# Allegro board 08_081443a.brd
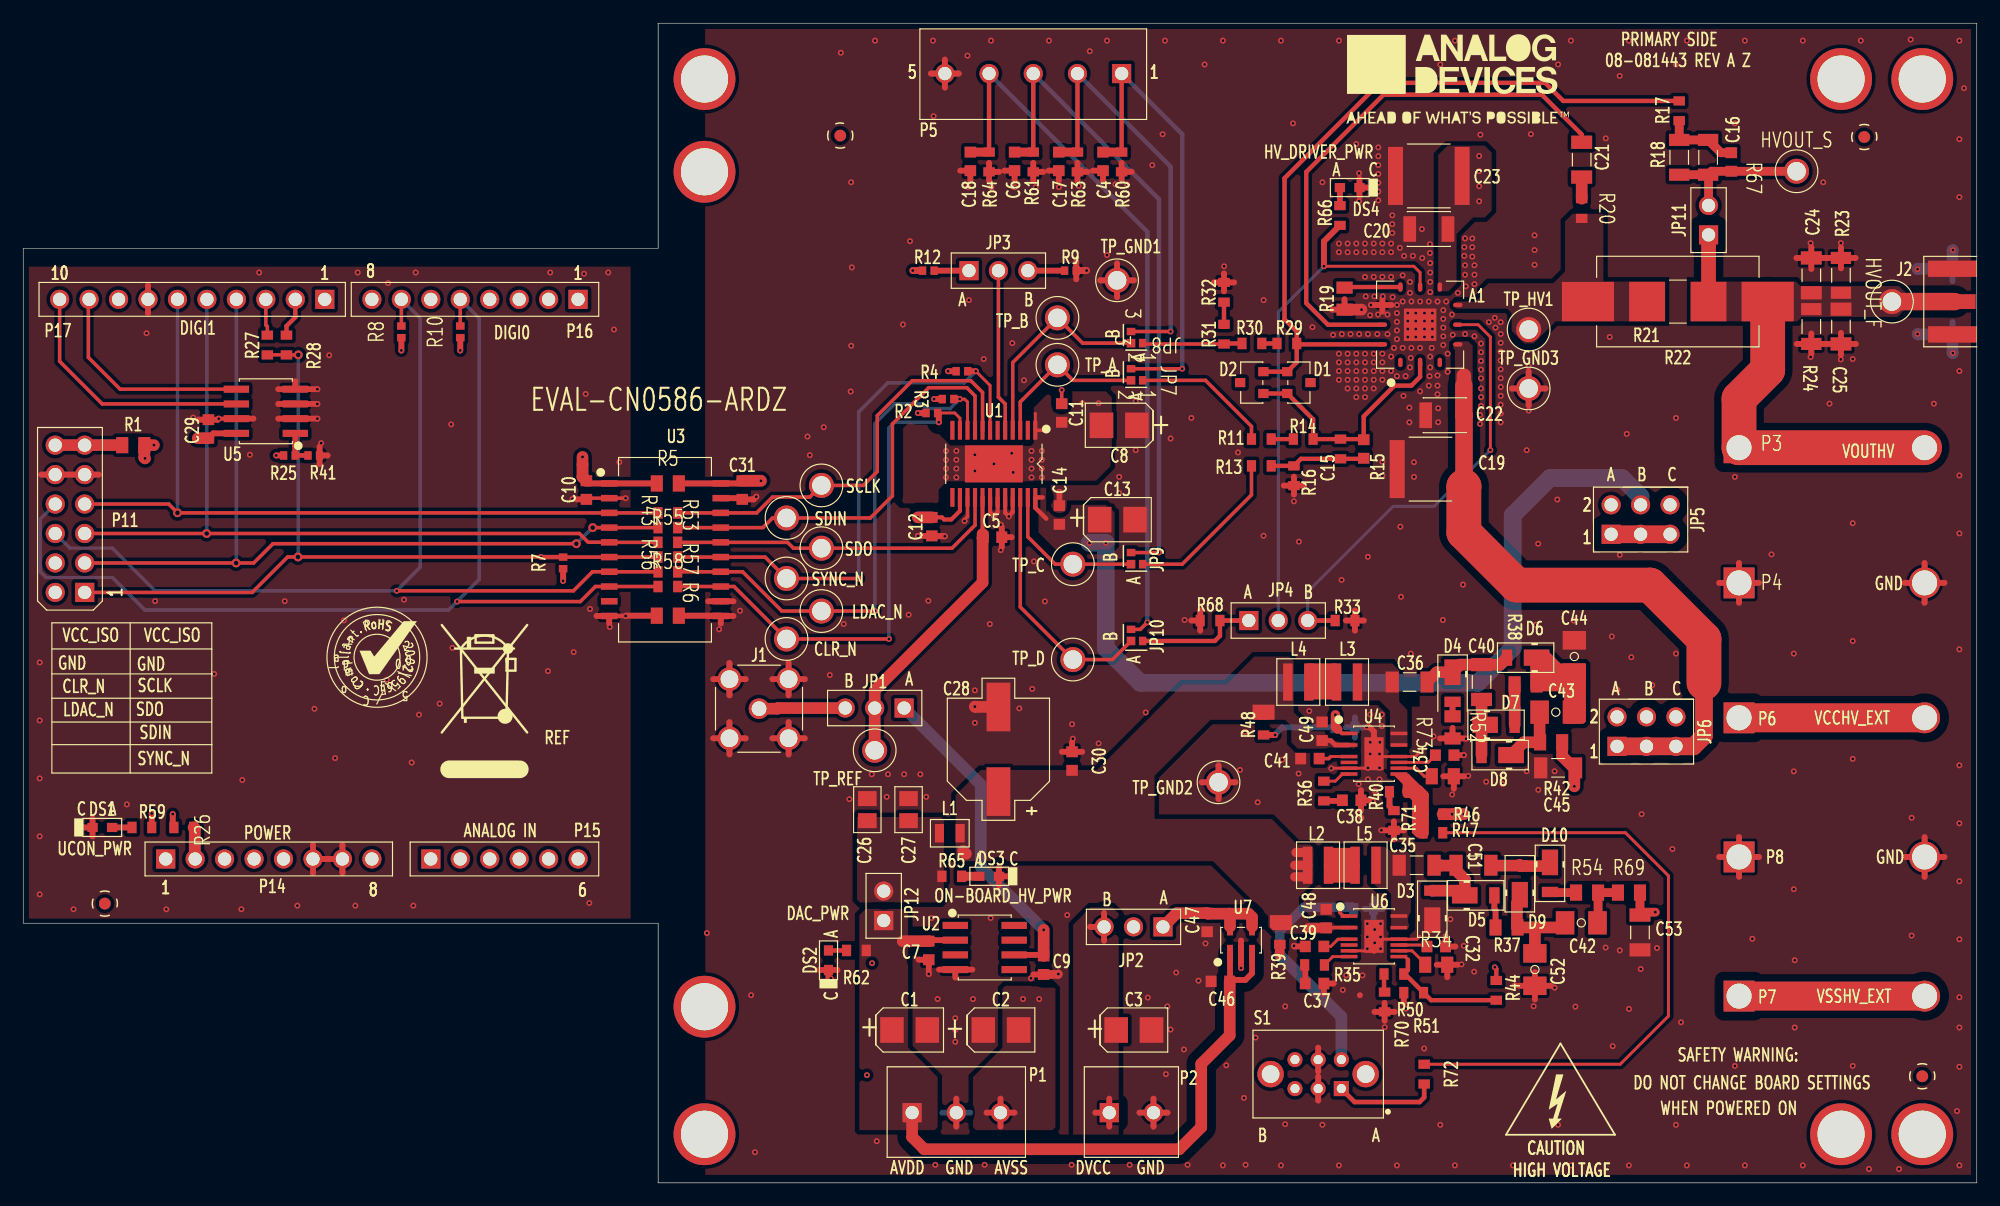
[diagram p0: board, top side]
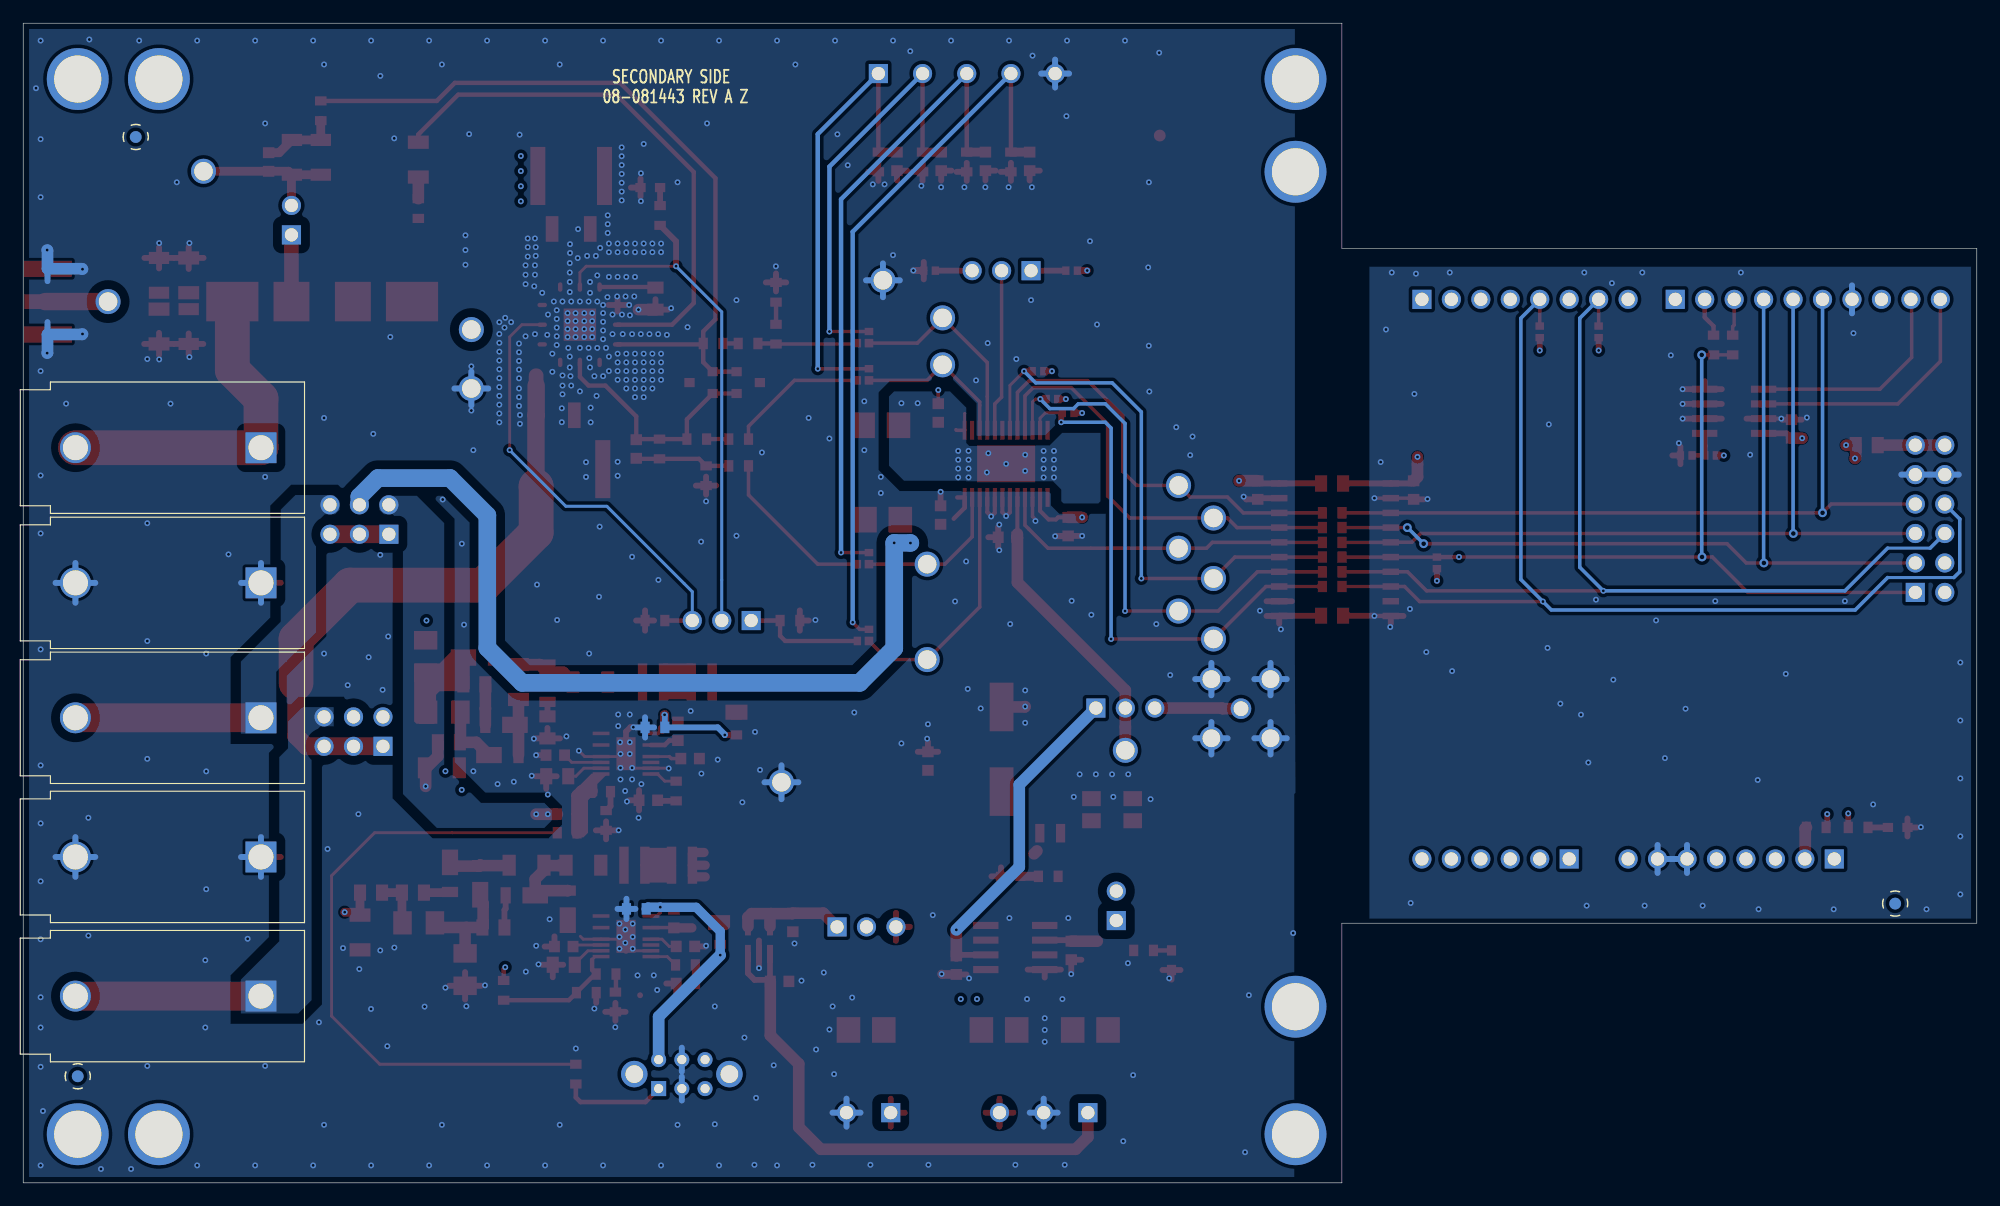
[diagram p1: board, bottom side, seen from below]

Outline 168.45 x 100 mm; copper layers: TOP, L2_GND, L3_PWR, BOTTOM. Coordinates in mm from the lower left corner of the outline.
Outline path: 0,80.59 0,22.39 54.74,22.39 54.74,0 168.45,0 168.45,100 54.74,100 54.74,80.59 0,80.59

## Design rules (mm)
constraint set DEFAULT: min track width 0.203
net group 200V: nets 15V_FLT AVSS UNNAMED_5_ADHV4702_I35_VCC UNNAMED_5_ADHV4702_I35_VEE VCCHV_EXT

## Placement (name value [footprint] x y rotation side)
A1  ADHV4702-1BCPZ  [QFN12_7X7_PAD2_8X2_8]  120.45 74 0 top
C1  10uF  [C3528]  76.43 13.18 0 top
C2  10uF  [C3528]  84.31 13.18 0 top
C3  10uF  [C3528]  95.77 13.18 0 top
C4  200pF  [C0603]  93.11 88.08 270 top
C5  0.1uF  [C0603]  83.58 55.67 180 top
C6  200pF  [C0603]  85.48 88.08 270 top
C7  0.1uF  [C0603]  78.08 20.04 90 top
C8  10uF  [C3528]  94.5 65.33 180 top
C9  0.1uF  [C0603]  87.99 18.77 90 top
C10  0.1uF  [C0603]  48.56 59.74 270 top
C11  0.1uF  [C0603]  89.55 66.39 90 top
C12  0.1uF  [C0603]  78.35 56.59 90 top
C13  10uF  [C3528]  94.35 57.19 0 top
C14  0.1uF  [C0603]  89.34 57.59 270 top
C15  2pF  [C0603]  115.59 63.28 270 top
C16  2pF  [C0603]  147.28 88.03 270 top
C17  200pF  [C0603]  89.29 88.08 270 top
C18  200pF  [C0603]  81.67 88.08 270 top
C19  2.2uF  [C2220-4]  121.35 61.55 0 top
C20  0.1uF  [C1210H87]  121.2 82.26 180 top
C21  100pF  [C1206]  134.38 88.23 90 top
C22  0.1uF  [C1210H87]  122.57 66.19 180 top
C23  2.2uF  [C2220-4]  121.2 86.83 180 top
C24  100pF  [C1206]  154.18 78.26 90 top
C25  100pF  [C1206]  156.74 73.84 270 top
C26  4.7uF  [C0805H53]  72.78 32.18 270 top
C27  4.7uF  [C0805H53]  76.34 32.18 270 top
C28  68uF  [CPLSMSQ327H413]  84.09 37.39 90 top
C29  0.1uF  [C0603]  15.97 65.01 90 top
C30  10uF  [C0603]  90.44 36.37 270 top
C31  0.1uF  [C0603]  62 59.74 270 top
C32  0.22uF  [C0603]  121.84 20.38 0 top
C34  0.22uF  [C0603]  122.57 36.88 0 top
C35  0.1UF  [C1206]  120.14 27.39 0 top
C36  0.1UF  [C1206]  119.55 43.19 0 top
C37  2200pF  [C0603]  111.35 17.19 0 top
C38  2200pF  [C0603]  114.55 32.99 0 top
C39  1uF  [C0603]  111.35 20.39 180 top
C40  0.1UF  [C1206]  125.75 43.19 270 top
C41  1uF  [C0603]  110.94 36.59 180 top
C42  0.22UF  [C1206H71]  134.35 22.42 180 top
C43  0.22UF  [C1206H71]  132.15 40.59 0 top
C44  0.22UF  [C1206H71]  133.75 45.39 90 top
C45  0.1UF  [C1206]  132.35 35.79 180 top
C46  2.2uF  [C0603]  103.23 17.37 180 top
C47  2.2uF  [C0603]  102.09 22.45 270 top
C48  1uF  [C0603]  112.35 22.79 90 top
C49  1uF  [C0603]  112 38.94 90 top
C51  0.1UF  [C1206]  125.05 27.39 0 top
C52  0.22UF  [C1206H71]  130.35 18.39 270 top
C53  0.1UF  [C1206]  139.41 21.59 270 top
CLR_N  WHT  [CNLOOPTP]  65.82 46.9 0 top
D1  BAV199LT1G  [SOT23-M3]  109.99 69.01 270 top
D2  BAV199LT1G  [SOT23-M3]  105.93 69.01 90 top
D3  DFLS1150-7  [POWERDI123]  121.5 23.59 90 top
D4  DFLS1150-7  [POWERDI123]  123.25 43.09 270 top
D5  DFLS1150-7  [POWERDI123]  125.24 24.79 0 top
D6  DFLS1150-7  [POWERDI123]  129.55 45.29 180 top
D7  DFLS1150-7  [POWERDI123]  126.99 39.49 0 top
D8  DFLS1150-7  [POWERDI123]  127.35 36.89 180 top
D9  DFLS1150-7  [POWERDI123]  129.04 25.79 90 top
D10  DFLS1150-7  [POWERDI123]  131.65 26.69 270 top
DS1  SML-D12P8WT86  [LED0603_A]  6.82 30.65 0 top
DS2  SML-D12P8WT86  [LED0603_A]  69.44 19.19 90 top
DS3  SML-D12P8WT86  [LED0603_A]  83.29 26.43 180 top
DS4  SML-D12P8WT86  [LED0603_A]  114.38 85.83 180 top
HVOUT_F  RED  [CNLOOPTP]  161.13 75.99 0 top
HVOUT_S  RED  [CNLOOPTP]  152.9 87.23 0 top
J1  1-1337482-0  [CNBNCSQ276H299]  63.45 40.89 0 top
J2  SMA-J-P-H-ST-EM1  [CNSAMTECSMA-JPX-ST-EM1-MKT]  168.45 75.99 0 top
JP1  M20-9990345  [CNHDR1X3H340]  75.96 40.94 180 top
JP2  M20-9990345  [CNHDR1X3H340]  98.28 22.07 180 top
JP3  M20-9990345  [CNHDR1X3H340]  81.55 78.66 0 top
JP4  M20-9990345  [CNHDR1X3H340]  105.68 48.49 0 top
JP5  TSW-103-07-G-D  [CNTHMHDR2X3L300W200H343_TL]  136.92 55.93 0 top
JP6  TSW-103-07-G-D  [CNTHMHDR2X3L300W200H343_TL]  137.43 37.64 0 top
JP7  0  [3PINJUMPER_0402]  95.52 69.2 270 top
JP8  0  [3PINJUMPER_0402]  95.52 72.41 270 top
JP9  0  [3PINJUMPER_0402]  95.52 53.35 270 top
JP10  0  [3PINJUMPER_0402]  95.52 46.73 270 top
JP11  TSW-102-08-G-S  [CNSAMTEC1X2H330LD36]  145.32 83.02 90 top
JP12  TSW-102-08-G-S  [CNSAMTEC1X2H330LD36]  74.2 23.89 90 top
L1  0.47UH  [L0806H39]  79.9 30.15 0 top
L2  6.8UH  [LSML126W138H118]  111.65 27.39 0 top
L3  6.8UH  [LSML126W138H118]  114.15 43.19 0 top
L4  6.8UH  [LSML126W138H118]  109.95 43.19 0 top
L5  6.8UH  [LSML126W138H118]  115.75 27.39 0 top
LDAC_N  WHT  [CNLOOPTP]  68.83 49.31 0 top
NOREF  -  []  30.51 45.32 0 top
NOREF#2  -  [unnamed#2]  156.75 95.19 0 top
NOREF#3  -  []  54.74 100 0 top
NOREF#4  -  [unnamed#2]  58.75 15.19 0 top
NOREF#5  -  [unnamed#2]  163.75 9.19 0 top
NOREF#6  -  []  0.01 80.59 0 top
NOREF#7  -  []  54.74 0 0 top
NOREF#8  -  []  54.74 0 0 top
NOREF#9  -  []  58.75 4.19 0 top
NOREF#10  -  []  168.45 0 90 top
NOREF#11  -  [unnamed#2]  163.75 4.19 0 top
NOREF#12  -  []  -109.94 -160.87 0 top
NOREF#13  -  []  58.75 4.19 0 top
NOREF#14  -  []  0.01 80.59 0 top
NOREF#15  -  [unnamed#2]  58.75 87.19 0 top
NOREF#16  -  []  -109.94 -158.67 0 top
NOREF#17  -  [unnamed#2]  163.75 95.19 0 top
NOREF#18  -  []  123.71 95.17 0 top
NOREF#19  -  []  -114.94 -160.87 0 top
NOREF#20  -  [unnamed#2]  156.75 4.19 0 top
NOREF#21  -  []  168.45 0 0 top
NOREF#22  -  []  132.3 6.94 0 top
NOREF#23  -  []  49.04 51.79 0 top
NOREF#24  -  [unnamed#2]  58.75 4.19 0 top
NOREF#25  -  [unnamed#2]  70.45 90.31 90 top
NOREF#26  -  [unnamed#2]  158.74 90.19 0 top
NOREF#27  -  []  0.01 22.39 0 top
NOREF#28  -  [unnamed#2]  7.04 24.08 0 top
NOREF#29  -  []  95.9 110.28 0 top
NOREF#30  -  []  0.01 22.39 0 top
NOREF#31  -  []  267.09 85.39 0 top
NOREF#32  -  []  227.62 89.09 0 top
NOREF#33  -  [unnamed#2]  58.75 95.19 0 top
NOREF#34  -  []  91.95 102.54 0 top
NOREF#35  -  [unnamed#2]  163.75 9.19 180 bottom
NOREF#36  -  [unnamed#2]  7.04 24.08 180 bottom
NOREF#37  -  [unnamed#2]  158.74 90.19 180 bottom
P1  1727023  [CNHDR1X3H335]  76.65 6.05 0 top
P2  1727010  [CNTH1X2H335_A]  93.65 6.05 0 top
P3  A-2.107-R  [CNMULTICOMP-A2107]  147.94 63.39 0 bottom
P4  A-2.107-B  [CNMULTICOMP-A2107]  147.94 51.74 0 bottom
P5  1727049  [CNTH1X5H335]  94.71 95.66 180 top
P6  A-2.107-R  [CNMULTICOMP-A2107]  147.95 40.1 0 bottom
P7  A-2.107-BL  [CNMULTICOMP-A2107]  147.95 16.1 0 bottom
P8  A-2.107-B  [CNMULTICOMP-A2107]  147.95 28.1 0 bottom
P11  TSW-106-08-G-D  [CNHDR2X6H330LD35]  5.3 50.91 90 top
P14  SSQ-108-03-G-S  [CNSAMTECSSQ-108-XX-X-S]  12.29 27.93 0 top
P15  SSQ-106-03-G-S  [CNSAMTECSSQ-106-XX-X-S]  35.15 27.93 0 top
P16  SSQ-108-03-G-S  [CNSAMTECSSQ-108-XX-X-S]  47.85 76.19 180 top
P17  SSQ-110-03-G-S  [CNSAMTECSSQ-110-XX-X-S]  26 76.19 180 top
R1  0  [R0805]  9.49 63.61 0 top
R2  10K  [R0402]  78.35 66.39 0 top
R3  10K  [R0402]  79.75 67.59 0 top
R4  10K  [R0402]  80.94 69.99 0 top
R5  0  [R0805]  55.58 60.31 0 top
R6  0  [R0805]  55.58 48.91 0 top
R7  10K  [R0402]  46.55 53.46 90 top
R8  10K  [R0402]  32.61 73.39 90 top
R9  10K  [R0402]  90.3 78.66 0 top
R10  10K  [R0402]  37.69 73.39 90 top
R11  4.7  [R0603]  106.76 64.14 0 top
R12  10K  [R0402]  78.05 78.66 180 top
R13  0  [R0603]  106.76 61.83 0 top
R14  2.49K  [R0603]  110.37 64.14 0 top
R15  49.9K  [R0603]  113.58 63.28 270 top
R16  0  [R0603]  109.57 60.98 270 top
R17  0  [R0603]  142.79 92.45 270 top
R18  100K  [R1206]  142.79 88.44 270 top
R19  50K  [R0805]  113.93 76.25 270 top
R20  20K  [R0603]  134.38 84.02 270 top
R21  0  [R2512H43]  142.67 75.99 0 top
R22  0.82  [R5329]  142.67 75.99 0 top
R23  20K  [R1206]  156.74 78.26 90 top
R24  20K  [R1206]  154.18 73.84 270 top
R25  10K  [R0402]  22.95 62.73 0 top
R26  0  [R0603]  13.85 30.65 180 top
R27  0  [R0603]  21.05 72.25 90 top
R28  0  [R0603]  22.7 72.25 90 top
R29  2.49K  [R0603]  108.96 72.38 0 top
R30  10  [R0603]  105.95 72.38 0 top
R31  2.49K  [R0603]  103.54 73.19 90 top
R32  0  [R0603]  103.54 76.8 90 top
R33  200K  [R0603]  113.97 48.49 0 top
R34  107K  [R0805]  121.84 18.81 0 top
R35  200K  [R0603]  111.35 18.79 180 top
R36  200K  [R0603]  112.15 33.79 270 top
R37  20  [R0805]  127.9 22.02 0 top
R38  20  [R0805]  129.55 42.99 0 top
R39  1MEG  [R0603]  108.36 21.41 270 top
R40  14.7K  [R0603]  118.66 33.73 180 top
R41  0  [R0402]  25.05 62.73 180 top
R42  47  [R0805]  131.74 37.99 0 top
R43  22  [R0603]  55.58 57.77 0 top
R44  1MEG  [R0603]  127.02 16.6 270 top
R45  162K  [R0603]  115.58 23.62 0 bottom
R46  1MEG  [R0603]  121.55 31.79 180 top
R47  16.9K  [R0603]  121.55 30.19 0 top
R48  1MEG  [R0603]  106.95 39.47 270 top
R49  162K  [R0603]  113.97 39.27 0 bottom
R50  7.32K  [R0603]  118.19 18 180 top
R51  8.2K  [R0603]  119.89 16.4 180 top
R52  20  [R0805]  123.25 39.27 270 top
R53  22  [R0603]  55.58 56.5 0 top
R54  20  [R0805]  134.84 25.03 0 top
R55  22  [R0603]  55.58 55.23 0 top
R56  22  [R0603]  55.58 53.96 0 top
R57  22  [R0603]  55.58 52.69 0 top
R58  22  [R0603]  55.58 51.42 0 top
R59  191  [R0603]  10.23 30.65 180 top
R60  2K  [R0603]  94.71 88.03 270 top
R61  2K  [R0603]  87.09 88.03 270 top
R62  2.49K  [R0603]  71.84 20.04 180 top
R63  2K  [R0603]  90.9 88.03 270 top
R64  2K  [R0603]  83.28 88.03 270 top
R65  2.49K  [R0603]  80.06 26.43 0 top
R66  590  [R0603]  113.53 83.42 90 top
R67  100K  [R1206]  145.28 88.44 270 top
R68  2.49K  [R0603]  102.34 48.49 180 top
R69  47  [R0805]  138.46 25.03 0 top
R70  0  [R0603]  117.39 15.6 270 top
R71  0  [R0603]  118.19 31.25 270 top
R72  0  [R0603]  120.8 9.38 270 top
R73  107K  [R0805]  122.4 35.06 0 top
S1  OS202011MS2QN1  [SWTHL339W268H342]  113.66 8.13 180 top
SCLK  WHT  [CNLOOPTP]  68.83 60.14 0 top
SDIN  WHT  [CNLOOPTP]  65.82 57.33 0 top
SDO  WHT  [CNLOOPTP]  68.83 54.72 0 top
SYNC_N  WHT  [CNLOOPTP]  65.82 52.12 0 top
TP_A  RED  [CNLOOPTP]  89.17 70.54 0 top
TP_B  RED  [CNLOOPTP]  89.17 74.59 0 top
TP_C  RED  [CNLOOPTP]  90.51 53.35 0 top
TP_D  RED  [CNLOOPTP]  90.51 45.12 0 top
TP_GND1  BLK  [CNLOOPTP]  94.32 77.83 0 top
TP_GND2  BLK  [CNLOOPTP]  103.07 34.54 0 top
TP_GND3  BLK  [CNLOOPTP]  129.81 68.5 0 top
TP_HV1  RED  [CNLOOPTP]  129.81 73.58 0 top
TP_REF  RED  [CNLOOPTP]  73.42 37.3 0 top
U1  AD5754RBREZ  [TSSOP24-3]  83.7 62 180 top
U2  ADR441BRZ  [SO8]  82.91 20.29 270 top
U3  ADUM4151BRIZ  [SO20WBH104]  55.34 54.6 270 top
U4  LT8365MSE  [MSOP16_PAD2_845X1_651_12P]  116.47 37.01 270 top
U5  24LC64-I/SN  [SO8]  20.92 66.54 90 top
U6  LT8365MSE  [MSOP16_PAD2_845X1_651_12P]  116.47 21.26 270 top
U7  ADP7142AUJZ-3.3  [TSOT-5]  105.01 20.93 0 top

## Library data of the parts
A1 = ADHV4702: User Part Number: UPN; Tolerance: N/A; alternate symbols: (QFN12_7X7_PAD2_8X2_8); tolerance: N/A
C1-C3 C8 C13 = CAPP: User Part Number: UPN; Tolerance: 10; alternate symbols: (C3528); tolerance: 10
C4 C6 C17 C18 = CAP: User Part Number: UPN; Tolerance: 1; alternate symbols: (C0603); tolerance: 1
C5 C7 C9-C12 C14 C29 C31 C32 C34 C37-C39 C41 C46-C49 = CAP: User Part Number: UPN; Tolerance: 10; alternate symbols: (C0603); tolerance: 10
C15 C16 = CAP: User Part Number: UPN; Tolerance: 0.1pF; alternate symbols: (C0603); tolerance: 0.1pF
C19 C23 = CAP: Tolerance: 10; User Part Number: UPN; alternate symbols: (C2220-4); tolerance: 10
C20 C22 = CAP: Tolerance: 10; User Part Number: UPN; alternate symbols: (C1210H87); tolerance: 10
C21 C24 C25 = CAP: User Part Number: UPN; Tolerance: 5; alternate symbols: (C1206); tolerance: 5
C26 C27 = CAP: Tolerance: 10; User Part Number: UPN; alternate symbols: (C0805H53); tolerance: 10
C28 = CAPP: User Part Number: UPN; Tolerance: 20; alternate symbols: (CPLSMSQ327H413); tolerance: 20
C30 = CAP: User Part Number: UPN; Tolerance: 20; alternate symbols: (C0603); tolerance: 20
C35 C36 C40 C45 C51 C53 = CAP: User Part Number: UPN; Tolerance: 10; alternate symbols: (C1206); tolerance: 10
C42-C44 C52 = CAP: Tolerance: 10; User Part Number: UPN; alternate symbols: (C1206H71); tolerance: 10
CLR_N HVOUT_F HVOUT_S LDAC_N SCLK SDIN SDO SYNC_N TP_A TP_B TP_C TP_D TP_GND1-TP_GND3 TP_HV1 TP_REF = CNTP1P: User Part Number: UPN; Tolerance: N/A; alternate symbols: (CNLOOPTP); tolerance: N/A
D1 D2 = DIO3P_V3: User Part Number: UPN; Tolerance: N/A; alternate symbols: (SOT23-M3); tolerance: N/A
D3-D10 = DIOSCHOTTKY: User Part Number: UPN; Tolerance: N/A; alternate symbols: (POWERDI123); tolerance: N/A
DS1-DS4 = DIOLED: User Part Number: UPN; Tolerance: N/A; alternate symbols: (LED0603_A); tolerance: N/A
J1 = CNBNC5P: Tolerance: N/A; User Part Number: UPN; alternate symbols: (CNBNCSQ276H299); tolerance: N/A
J2 = CNBNC5P: Tolerance: N/A; User Part Number: UPN; alternate symbols: (CNSAMTECSMA-JPX-ST-EM1-MKT); tolerance: N/A
JP1-JP4 = CN3P_JMPRSHRT: Tolerance: N/A; User Part Number: UPN; alternate symbols: (CNHDR1X3H340); tolerance: N/A
JP5 JP6 = CN6P_ODD_EVEN: User Part Number: UPN; Tolerance: N/A; alternate symbols: (CNTHMHDR2X3L300W200H343_TL); tolerance: N/A
JP7-JP10 = RESJMPR_3P: User Part Number: UPN; Tolerance: JUMPER; alternate symbols: (3PINJUMPER_0402); tolerance: JUMPER
JP11 JP12 = CN2P: User Part Number: UPN; Tolerance: N/A; alternate symbols: (CNSAMTEC1X2H330LD36); tolerance: N/A
L1 = IND: Tolerance: 20; User Part Number: UPN; alternate symbols: (L0806H39); tolerance: 20
L2-L5 = IND: Tolerance: 20; User Part Number: UPN; alternate symbols: (LSML126W138H118); tolerance: 20
P1 = CN3P: Tolerance: N/A; User Part Number: UPN; alternate symbols: (CNHDR1X3H335); tolerance: N/A
P2 = CN2P: Tolerance: N/A; User Part Number: UPN; alternate symbols: (CNTH1X2H335_A); tolerance: N/A
P3 P4 P6-P8 = CN2P: User Part Number: UPN; Tolerance: N/A; alternate symbols: (CNMULTICOMP-A2107); tolerance: N/A
P5 = CN5P: Tolerance: N/A; User Part Number: UPN; alternate symbols: (CNTH1X5H335); tolerance: N/A
P11 = CN12P_V3: Tolerance: N/A; User Part Number: UPN; alternate symbols: (CNHDR2X6H330LD35); tolerance: N/A
P14 P16 = CN8P_A: User Part Number: UPN; Tolerance: N/A; alternate symbols: (CNSAMTECSSQ-108-XX-X-S); tolerance: N/A
P15 = CN6P: User Part Number: UPN; Tolerance: N/A; alternate symbols: (CNSAMTECSSQ-106-XX-X-S); tolerance: N/A
P17 = CN10P: User Part Number: UPN; Tolerance: N/A; alternate symbols: (CNSAMTECSSQ-110-XX-X-S); tolerance: N/A
R1 R5 R6 = RES: User Part Number: UPN; Tolerance: N/A; alternate symbols: (R0805); tolerance: N/A
R2-R4 R7-R10 R12 R25 = RES: User Part Number: UPN; Tolerance: 5; alternate symbols: (R0402); tolerance: 5
R11 R20 R30 R33 R35 R36 R45 R47 R49-R51 R59-R61 R63 R64 R66 = RES: User Part Number: UPN; Tolerance: 1; alternate symbols: (R0603); tolerance: 1
R13 R16 R17 R26 R27 R32 R70-R72 = RES: User Part Number: UPN; Tolerance: JUMPER; alternate symbols: (R0603); tolerance: JUMPER
R14 R15 R29 R31 R62 R65 R68 = RES: User Part Number: UPN; Tolerance: 0.1; alternate symbols: (R0603); tolerance: 0.1
R18 R67 = RES: User Part Number: UPN; Tolerance: 0.1; alternate symbols: (R1206); tolerance: 0.1
R19 R42 R69 = RES: User Part Number: UPN; Tolerance: 0.1; alternate symbols: (R0805); tolerance: 0.1
R21 = RES: User Part Number: UPN; Tolerance: N/A; alternate symbols: (R2512H43); tolerance: N/A
R22 = RES: Tolerance: 5; User Part Number: UPN; alternate symbols: (R5329); tolerance: 5
R23 R24 = RES: User Part Number: UPN; Tolerance: 1; alternate symbols: (R1206); tolerance: 1
R28 = RES: User Part Number: UPN; Tolerance: N/A; alternate symbols: (R0603); tolerance: N/A
R34 R37 R38 R52 R54 R73 = RES: User Part Number: UPN; Tolerance: 1; alternate symbols: (R0805); tolerance: 1
R39 R44 R46 R48 = RES: User Part Number: UPN; Tolerance: 5; alternate symbols: (R0603); tolerance: 5
R40 R43 R53 R55-R58 = RES: User Part Number: UPN; Tolerance: 0.5; alternate symbols: (R0603); tolerance: 0.5
R41 = RES: User Part Number: UPN; Tolerance: JUMPER; alternate symbols: (R0402); tolerance: JUMPER
S1 = SWDPDT_V2: Tolerance: N/A; User Part Number: UPN; alternate symbols: (SWTHL339W268H342); tolerance: N/A
U1 = AD57X4R: Tolerance: N/A; User Part Number: UPN; alternate symbols: (TSSOP24-3); tolerance: N/A
U2 = ADR441: Tolerance: N/A; User Part Number: UPN; alternate symbols: (SO8); tolerance: N/A
U3 = ADUM4151: Tolerance: N/A; User Part Number: UPN; alternate symbols: (SO20WBH104); tolerance: N/A
U4 U6 = ICLTC8365: Tolerance: N/A; User Part Number: UPN; alternate symbols: (MSOP16_PAD2_845X1_651_12P); tolerance: N/A
U5 = IC24XX64: Tolerance: N/A; User Part Number: UPN; alternate symbols: (SO8); tolerance: N/A
U7 = ADP7142_V2: User Part Number: UPN; Tolerance: N/A; alternate symbols: (TSOT-5); tolerance: N/A

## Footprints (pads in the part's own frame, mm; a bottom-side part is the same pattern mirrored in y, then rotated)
3PINJUMPER_0402
  rect 0.737x0.635 smd: 1(0,1.001)
  rect 0.737x0.737 smd: 2(0,0)
  rect 0.635x0.737 smd: 3(-1.001,0)
C0603
  rect 0.94x0.991 smd: 1(-0.8,0) 2(0.8,0)
C0805H53
  rect 1.295x1.6 smd: 1(-0.953,0) 2(0.953,0)
C1206
  rect 1.143x1.803 smd: 1(-1.501,0) 2(1.501,0)
C1206H71
  rect 1.6x2.007 smd: 1(-1.397,0) 2(1.397,0)
C1210H87
  rect 1.092x2.21 smd: 1(-1.646,0) 2(1.646,0)
C2220-4
  rect 1.295x5.004 smd: 1(-2.873,0) 2(2.873,0)
C3528
  rect 2.032x2.21 smd: N(1.524,0) P(-1.524,0)
CNBNCSQ276H299
  round 1.778 hole 1.27: 1(0,0)
  round 2.032 hole 1.524: 2(-2.55,2.55) 3(2.55,2.55) 4(2.55,-2.55) 5(-2.55,-2.55)
CNHDR1X3H335
  rect 1.651x1.651 hole 1.143: 1(0,0)
  round 1.651 hole 1.143: 2(3.81,0) 3(7.62,0)
CNHDR1X3H340
  rect 1.651x1.651 hole 1.143: 1(0,0)
  round 1.651 hole 1.143: 2(2.54,0) 3(5.08,0)
CNHDR2X6H330LD35
  rect 1.651x1.651 hole 1.143: 1(0,0)
  round 1.651 hole 1.143: 2(2.54,0) 3(5.08,0) 4(7.62,0) 5(10.16,0) 6(12.7,0) 7(0,2.54) 8(2.54,2.54) 9(5.08,2.54) 10(7.62,2.54) 11(10.16,2.54) 12(12.7,2.54)
CNLOOPTP
  round 2.159 hole 1.6: 1(0,0)
CNMULTICOMP-A2107
  rect 2.667x2.667 hole 2.159: 1(0,0)
  round 2.667 hole 2.159: 2(15.999,0)
CNSAMTEC1X2H330LD36
  rect 1.651x1.651 hole 1.143: 1(-1.27,0)
  round 1.651 hole 1.143: 2(1.27,0)
CNSAMTECSMA-JPX-ST-EM1-MKT
  rect 3.581x1.27 smd: 1(-1.892,0)
  rect 4.191x1.372 smd: 2(-2.095,2.832) 3(-2.095,2.832) 4(-2.095,-2.832) 5(-2.095,-2.832)
CNSAMTECSSQ-106-XX-X-S
  rect 1.651x1.651 hole 1.143: 1(0,0)
  round 1.651 hole 1.143: 2(2.54,0) 3(5.08,0) 4(7.62,0) 5(10.16,0) 6(12.7,0)
CNSAMTECSSQ-108-XX-X-S
  rect 1.651x1.651 hole 1.143: 1(0,0)
  round 1.651 hole 1.143: 2(2.54,0) 3(5.08,0) 4(7.62,0) 5(10.16,0) 6(12.7,0) 7(15.24,0) 8(17.78,0)
CNSAMTECSSQ-110-XX-X-S
  rect 1.651x1.651 hole 1.143: 1(0,0)
  round 1.651 hole 1.143: 2(2.54,0) 3(5.08,0) 4(7.62,0) 5(10.16,0) 6(12.7,0) 7(15.24,0) 8(17.78,0) 9(20.32,0) 10(22.86,0)
CNTH1X2H335_A
  rect 1.651x1.651 hole 1.143: 1(0,0)
  round 1.651 hole 1.143: 2(3.81,0)
CNTH1X5H335
  rect 1.651x1.651 hole 1.143: 1(0,0)
  round 1.651 hole 1.143: 2(3.81,0) 3(7.62,0) 4(11.43,0) 5(15.24,0)
CNTHMHDR2X3L300W200H343_TL
  rect 1.651x1.651 hole 1.143: 1(0,0)
  round 1.651 hole 1.143: 2(0,2.54) 3(2.54,0) 4(2.54,2.54) 5(5.08,0) 6(5.08,2.54)
CPLSMSQ327H413
  rect 4.191x2.057 smd: N(3.65,0) P(-3.65,0)
L0806H39
  rect 0.787x1.6 smd: 1(-0.894,0) 2(0.894,0)
LED0603_A
  rect 0.889x0.787 smd: A(0.843,0) C(-0.843,0)
LSML126W138H118
  rect 0.813x3.2 smd: 1(-0.902,0) 2(0.902,0)
MSOP16_PAD2_845X1_651_12P
  rect 0.305x1.448 smd: 1(-1.75,-2.149) 3(-0.749,-2.149) 5(0.249,-2.149) 6(0.749,-2.149) 7(1.25,-2.149) 8(1.75,-2.149) 9(1.75,2.149) 10(1.25,2.149) 11(0.749,2.149) 12(0.249,2.149) 14(-0.749,2.149) 16(-1.75,2.149)
  rect 2.845x1.651 smd: PAD(0,0)
POWERDI123
  rect 0.889x1.397 smd: A(1.605,0)
  rect 2.21x1.397 smd: C(-0.945,0)
QFN12_7X7_PAD2_8X2_8
  oval 0.381x0.813 smd: 1(-1.699,-3.249) 2(0,-3.249) 3(1.699,-3.249) 7(1.699,3.249) 8(0,3.249) 9(-1.699,3.249)
  oval 0.813x0.381 smd: 4(3.249,-1.699) 5(3.249,0) 6(3.249,1.699) 10(-3.249,1.699) 11(-3.249,0) 12(-3.249,-1.699)
  rect 2.794x2.794 smd: PAD(0,0)
R0402
  rect 0.635x0.737 smd: 1(-0.5,0) 2(0.5,0)
R0603
  rect 0.787x0.991 smd: 1(-0.851,0) 2(0.851,0)
R0805
  rect 1.041x1.397 smd: 1(-0.95,0) 2(0.95,0)
R1206
  rect 1.041x1.753 smd: 1(-1.501,0) 2(1.501,0)
R2512H43
  rect 3.099x3.404 smd: 1(-2.649,0) 2(2.649,0)
R5329
  rect 4.496x3.404 smd: 1(-7.747,0) 2(7.747,0)
SO8
  rect 0.61x2.184 smd: 1(-1.905,-2.54) 2(-0.635,-2.54) 3(0.635,-2.54) 4(1.905,-2.54) 5(1.905,2.54) 6(0.635,2.54) 7(-0.635,2.54) 8(-1.905,2.54)
SO20WBH104
  rect 0.559x1.422 smd: 1(-5.715,-4.811) 2(-4.445,-4.811) 3(-3.175,-4.811) 4(-1.905,-4.811) 5(-0.635,-4.811) 6(0.635,-4.811) 7(1.905,-4.811) 8(3.175,-4.811) 9(4.445,-4.811) 10(5.715,-4.811) 11(5.715,4.811) 12(4.445,4.811) 13(3.175,4.811) 14(1.905,4.811) 15(0.635,4.811) 16(-0.635,4.811) 17(-1.905,4.811) 18(-3.175,4.811) 19(-4.445,4.811) 20(-5.715,4.811)
SOT23-M3
  rect 0.787x0.889 smd: 1(-0.94,-1.003) 2(0.94,-1.003) 3(0,1.003)
SWTHL339W268H342
  round 2.286 hole 1.524 unplated: (-2.101,-1.25) (6.101,-1.25)
  rect 1.295x1.295 hole 0.787: 1(0,0)
  round 1.295 hole 0.787: 2(1.999,0) 3(4,0) 4(0,-2.499) 5(1.999,-2.499) 6(4,-2.499)
TSOT-5
  rect 0.508x1.524 smd: 1(-0.95,-1.171) 2(0,-1.171) 3(0.95,-1.171) 4(0.95,1.171) 5(-0.95,1.171)
TSSOP24-3
  rect 0.356x1.626 smd: 1(-3.574,-2.896) 2(-2.926,-2.896) 3(-2.276,-2.896) 4(-1.626,-2.896) 5(-0.975,-2.896) 6(-0.325,-2.896) 7(0.325,-2.896) 8(0.975,-2.896) 9(1.626,-2.896) 10(2.276,-2.896) 11(2.926,-2.896) 12(3.574,-2.896) 13(3.574,2.896) 14(2.926,2.896) 15(2.276,2.896) 16(1.626,2.896) 17(0.975,2.896) 18(0.325,2.896) 19(-0.325,2.896) 20(-0.975,2.896) 21(-1.626,2.896) 22(-2.276,2.896) 23(-2.926,2.896) 24(-3.574,2.896)
  rect 5.004x3.2 smd: PAD(0,0)
unnamed#2
  round 5.334 hole 4.064 unplated: (0,0)

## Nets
15V_FLT: C28.P C30.2(N2) C48.1 C49.1 L1.2(N2) L2.1 L4.1 R39.1 R48.1 U4.3(VIN) U6.3(VIN)
15V_HV: C26.2(N2) C27.2(N2) JP12.2(N2) L1.1 R65.1
AVDD: C1.P C7.2(N2) C13.P C14.2(N2) C46.1 JP5.4 JP12.1 P1.1 R62.1 U1.24 U2.2 U7.1 U7.3
AVSS: C2.N(N2) C8.N(N2) C11.1 JP6.4 P1.3(N3) U1.1 U1.PAD
DVCC_DAC: C12.2(N2) C31.1 JP2.2 R2.1 R3.1 R4.1 R5.2(N2) R12.2(N2) U1.14 U3.20
GND: A1.10 A1.PAD C1.N(N2) C2.P C3.N(N2) C4.2(N2) C5.1 C6.2(N2) C7.1 C8.P C9.1 C11.2(N2) C12.1 C13.N(N2) C14.1 C17.2(N2) C18.2(N2) C19.1 C20.2(N2) C22.2(N2) C23.2(N2) C24.2(N2) C25.2(N2) C26.1 C27.1 C28.N(N2) C30.1 C31.2(N2) C32.2(N2) C34.2(N2) C37.2(N2) C38.2(N2) C39.2(N2) C41.2(N2) C44.2(N2) C45.2(N2) C46.2(N2) C47.2(N2) C48.2(N2) C49.2(N2) C52.2(N2) C53.2(N2) D3.C DS2.C DS3.C DS4.C J1.2 J1.3 J1.4 J1.5(SH4) J2.2 J2.3 J2.4 J2.5(SH4) P1.2 P2.2(N2) P4.1 P4.2(N2) P5.5(N5) P8.1 P8.2(N2) R6.2(N2) R9.2(N2) R16.2(N2) R19.2(N2) R23.2(N2) R24.2(N2) R32.2(N2) R33.2(N2) R34.2(N2) R45.2(N2) R49.2(N2) R51.2(N2) R52.2(N2) R60.2(N2) R61.2(N2) R63.2(N2) R64.2(N2) R68.2(N2) R70.2(N2) R71.2(N2) R73.2(N2) S1.2 S1.5 TP_GND1.1(N1) TP_GND2.1(N1) TP_GND3.1(N1) U1.15 U1.18 U1.19 U1.20 U1.21 U2.4 U3.11 U3.12 U3.19 U4.7 U4.12 U4.PAD U6.7 U6.12 U6.PAD U7.2
GND_ISO: C10.2(N2) C29.2(N2) DS1.C P11.5 P11.11 P14.6 P14.7 P17.7 R6.1 R41.1 U3.2 U3.10 U5.2 U5.3 U5.4 U5.7(WP)
VCCHV_EXT: JP5.6(N6) P6.1 P6.2(N2)
VCCHV_LT8365: C45.1 JP5.2 R42.2(N2) R46.1
VCCISO_EXT: C10.1 C29.1 R1.2(N2) R5.1 R7.1 R8.1 R10.1 R25.1 R26.2(N2) R59.1 U3.1 U5.8
VSSHV_EXT: JP6.6(N6) P7.1 P7.2(N2)
VSSHV_LT8365: C53.1 JP6.2 R44.1 R69.2(N2)
3P3V_EXT: C3.P JP2.3(S3) P2.1
3P3V_LDO: C47.1 JP2.1 U7.4 U7.5(VOUT)
A1_SHUTDOWN_N: A1.8 JP4.2 R66.1
BIN2SCOMP: JP3.2 U1.5
CLR_N: P11.10 P16.5 R10.2(N2) R58.1 U3.8
CLR_N_DAC: CLR_N.1(N1) R2.2(N2) R58.2(N2) U1.11 U3.13
DACA: JP7.1 R11.1
DACB: JP8.1 R30.1 R31.1
DACC: JP9.1 R13.1
DACD: JP4.1 JP10.1 R68.1
HVOUT_SENSE: C16.2(N2) HVOUT_S.1(N1) JP11.2(N2) R18.2(N2) R67.2(N2)
LDAC_N: P11.9 P16.7 R8.2(N2) R57.1 U3.7
LDAC_N_DAC: LDAC_N.1(N1) R3.2(N2) R57.2(N2) U1.10 U3.14
REF: J1.1 JP1.3(S3)
SCL: P17.10 U5.6
SCLK: P11.4 P17.6 R43.1 U3.3
SCLK_DAC: R43.2(N2) SCLK.1(N1) U1.8 U3.18
SDA: P17.9(N9) U5.5
SDIN: P11.2 P17.4 R53.1 U3.4
SDIN_DAC: R53.2(N2) SDIN.1(N1) U1.9 U3.17
SDO: P11.3 P17.5 R55.1 U3.5
SDO_DAC: R55.2(N2) SDO.1(N1) U1.16 U3.16
SYNC_N: P11.1 R7.2(N2) R27.1 R28.1 R56.1 U3.6
SYNC_N_DAC: R4.2(N2) R56.2(N2) SYNC_N.1(N1) U1.7 U3.15
TMP: A1.5 JP4.3(S3) R33.1
U4_RFB2: R72.2(N2) S1.1
U6_EN: R39.2(N2) R45.1 S1.4(NO2) U6.1
UNNAMED_2_AD57X4R_I19_REFINREFO: C5.2(N2) JP1.2 TP_REF.1(N1) U1.17
UNNAMED_2_AD57X4R_I19_VOUTA: JP7.2(COM) TP_A.1(N1) U1.3
UNNAMED_2_AD57X4R_I19_VOUTB: JP8.2(COM) TP_B.1(N1) U1.4
UNNAMED_2_AD57X4R_I19_VOUTC: JP9.2(COM) TP_C.1(N1) U1.23
UNNAMED_2_AD57X4R_I19_VOUTD: JP10.2(COM) TP_D.1(N1) U1.22(VOUTD)
UNNAMED_2_ADR441_I50_VOUT: C9.2(N2) JP1.1 U2.6(VOUT)
UNNAMED_2_CN3PJMPRSHRT_I28_S1: JP3.1 R12.1
UNNAMED_2_CN3PJMPRSHRT_I28_S3: JP3.3(S3) R9.1
UNNAMED_2_CN8PA_I284_N2: P14.2 R26.1
UNNAMED_2_CN10P_I292_N2: P17.2 R28.2(N2)
UNNAMED_2_CN10P_I292_N3: P17.3 R27.2(N2)
UNNAMED_2_CN12PV3_I158_VCC1: P11.6 P11.12(VCC2) R1.1
UNNAMED_2_DIOLED_I327_P: DS1.A(P) R59.2(N2)
UNNAMED_2_DIOLED_I330_P: DS2.A(P) R62.2(N2)
UNNAMED_2_DIOLED_I335_P: DS3.A(P) R65.2(N2)
UNNAMED_2_DIOLED_I337_P: DS4.A(P) R66.2(N2)
UNNAMED_2_IC24XX64_I297_A0: R25.2(N2) R41.2(N2) U5.1
UNNAMED_4_CAP_I184_N2: C35.2(N2) C51.1 D3.A(P) D5.C
UNNAMED_4_CAP_I188_N1: C42.1 R54.2(N2) R69.1
UNNAMED_4_CAP_I188_N2: C42.2(N2) C52.1 D9.C R37.2(N2)
UNNAMED_4_CAP_I194_N1: C32.1 U6.11
UNNAMED_4_CAP_I196_N1: C39.1 U6.5
UNNAMED_4_CAP_I198_N1: C37.1 R35.2(N2)
UNNAMED_4_CAP_I204_N1: C36.1 L3.2(N2) U4.14 U4.16
UNNAMED_4_CAP_I204_N2: C36.2(N2) C40.1 D4.C D6.A(P)
UNNAMED_4_CAP_I207_N2: C40.2(N2) D7.C D8.A(P)
UNNAMED_4_CAP_I211_N1: C43.1 D8.C R42.1
UNNAMED_4_CAP_I211_N2: C43.2(N2) C44.1 D6.C R38.2(N2)
UNNAMED_4_CAP_I220_N1: C41.1 U4.5
UNNAMED_4_CAP_I222_N1: C38.1 R36.2(N2)
UNNAMED_4_CAP_I227_N1: C34.1 U4.11
UNNAMED_4_CAP_I249_N2: C51.2(N2) D9.A(P) D10.C
UNNAMED_4_DIOSCHOTTKY_I186_P: D5.A(P) R37.1
UNNAMED_4_DIOSCHOTTKY_I203_P: D4.A(P) R52.1
UNNAMED_4_DIOSCHOTTKY_I209_P: D7.A(P) R38.1
UNNAMED_4_DIOSCHOTTKY_I252_P: D10.A(P) R54.1
UNNAMED_4_ICLTC8365_I179_FBX: R44.2(N2) R50.1 R51.1 U6.9
UNNAMED_4_ICLTC8365_I179_RT: R34.1 U6.10
UNNAMED_4_ICLTC8365_I179_SW1: C35.1 L5.2(N2) U6.14 U6.16
UNNAMED_4_ICLTC8365_I179_VC: R35.1 U6.8
UNNAMED_4_ICLTC8365_I200_EN: R48.2(N2) R49.1 U4.1
UNNAMED_4_ICLTC8365_I200_FBX: R40.1 R46.2(N2) R47.1 U4.9
UNNAMED_4_ICLTC8365_I200_RT: R73.1 U4.10
UNNAMED_4_ICLTC8365_I200_VC: R36.1 U4.8
UNNAMED_4_IND_I183_N2: L2.2(N2) L5.1
UNNAMED_4_IND_I205_N1: L3.1 L4.2(N2)
UNNAMED_4_RES_I219_N2: R40.2(N2) R71.1
UNNAMED_4_RES_I223_N2: R47.2(N2) R72.1
UNNAMED_4_RES_I233_N2: R50.2(N2) R70.1
UNNAMED_5_ADHV4702_I35_COMP: A1.11 C21.2(N2)
UNNAMED_5_ADHV4702_I35_IN: A1.12 D1.1(P) D2.2 R17.1 R29.2(N2)
UNNAMED_5_ADHV4702_I35_IN_1: A1.2 C15.1 D1.2 D2.1(P) R14.2(N2) R15.1
UNNAMED_5_ADHV4702_I35_OUT: A1.6 R20.2(N2) R21.1 R22.1 TP_HV1.1(N1)
UNNAMED_5_ADHV4702_I35_RADJ: A1.9 R19.1
UNNAMED_5_ADHV4702_I35_VCC: A1.7 C20.1 C23.1 JP5.1 JP5.3 JP5.5
UNNAMED_5_ADHV4702_I35_VEE: A1.4(VEE) C19.2(N2) C22.1 JP6.1 JP6.3 JP6.5
UNNAMED_5_CAP_I29_N1: C21.1 R20.1
UNNAMED_5_CAP_I34_N2: C15.2(N2) R13.2(N2) R15.2(N2) R16.1
UNNAMED_5_CAP_I38_N1: C16.1 R17.2(N2) R18.1 R67.1
UNNAMED_5_RES_I25_N1: R11.2(N2) R14.1
UNNAMED_5_RES_I46_N1: R29.1 R30.2(N2)
UNNAMED_5_RES_I48_N2: R31.2(N2) R32.1
VOA: C4.1 JP7.3 P5.1 R60.1
VOB: C17.1 JP8.3 P5.2 R63.1
VOC: C6.1 JP9.3 P5.3 R61.1
VOD: C18.1 JP10.3 P5.4 R64.1
VOUT_HV: C24.1 C25.1 HVOUT_F.1(N1) J2.1 JP11.1 P3.1 P3.2(N2) R21.2(N2) R22.2(N2) R23.1 R24.1

Pads without a net: A1 1 3; D1 3; D2 3; P11 7 8; P14 1 3 4 5 8; P15 1 2 3 4 5 6; P16 1 2 3 4 6 8; P17 1 8; S1 3 6; U1 2 6 12 13; U2 1 3 5 7 8; U3 9; U4 6; U6 6

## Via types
v1: diameter 0.508, hole 0.254, TOP to BOTTOM, 622 vias
v2: diameter 0.762, hole 0.406, TOP to BOTTOM, 7 vias

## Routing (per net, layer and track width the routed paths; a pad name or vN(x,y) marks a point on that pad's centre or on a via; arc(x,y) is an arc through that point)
15V_FLT: length 12.6
  TOP w0.3: 111.4,22.09 111.55,21.94 111.59,21.94 111.66,22.01 U6.3
  TOP w0.399: C49.1 112.75,38.14 113.13,37.75 U4.3
  TOP w0.8: L2.1 110.74,26.48 110.64,26.39 109.65,26.39 ; L2.1 109.65,27.39 ; L2.1 110.74,28.39 110.64,28.49 109.75,28.49 ; 110.79,21.99 C48.1
  TOP w1.001: 81.04,28.62 81.29,28.37
AVDD: length 132.4
  TOP w0.381: 88.21,57.27 87.27,58.21 U1.24 87.9,59.11
  TOP w0.5: 104.06,17.4 C46.1 ; 104.06,17.4 U7.1 ; 104.06,17.4 104.16,17.5 105.39,17.5 105.96,18.07 U7.3 ; C7.2 78.17,20.93 U2.2
  TOP w1.001: C7.2 75.83,20.84 ; P1.1 76.65,3.95 77.7,2.89 99.67,2.89 101.58,4.8 101.58,10.26 104.03,12.71 C46.1
  L3_PWR w0.508: 72.99,22.62 JP12.1 ; JP12.1 75.4,22.62 ; JP12.1 74.2,21.41
  BOTTOM w1.501: v1(91.95,55.17) 91.96,55.19 v1(93.34,55.19)
  BOTTOM w1.524: JP5.4 139.46,59.18 137.86,60.77 131.64,60.77 128.43,57.56 128.43,46.12 125.42,43.12 96.33,43.12 93.34,46.1 v1(93.34,55.19)
AVSS: length 7
  TOP w0.254: 87.26,66.34 87.27,66.33 87.27,64.9 U1.1
  TOP w0.305: 87.27,64.9 87.98,64.9 88.02,64.95
  TOP w0.508: P1.3 85.47,6.05 ; P1.3 84.27,7.25 ; P1.3 83.06,6.05 ; P1.3 84.27,4.85
  vias: v1(79.57,63.12) v1(79.57,62.35) v1(79.57,61.59) v1(79.57,60.83) v1(80.46,63.12) v1(80.46,62.35) v1(80.46,61.59) v1(80.46,60.83) v1(82.05,62.79) v1(82.05,61.39) v1(83.7,62) v1(85.23,62.91) v1(85.36,61.26) v1(86.21,15.85) v1(86.94,63.12) v1(86.94,62.35) v1(86.94,61.59) v1(86.94,60.83) v1(87.61,15.85) v1(87.83,63.12) v1(87.83,62.35) v1(87.83,61.59) v1(87.83,60.83) v1(91.33,67.23) v1(92.72,67.23)
DVCC_DAC: length 17.8
  TOP w0.351: U1.14 80.77,59.11 80.77,57.95 80.03,57.2 79.4,57.2 79.21,57.39 C12.2
  TOP w0.5: R4.1 v1(79.75,69.99) ; R3.1 v1(78.55,67.59) ; R2.1 v1(77.14,66.39)
  TOP w0.508: C31.1 61.78,60.31 U3.20 R5.2 56.43,60.31
  TOP w0.599: R12.2 77.54,78.67 v1(76.71,78.67)
  TOP w1.001: C12.2 v1(77.14,57.39)
  TOP w1.016: v1(63.61,60.54) C31.1
  L3_PWR w0.508: 95.74,20.87 JP2.2 95.74,23.27
GND: length 491.8
  TOP w0.249: v1(120.54,37.26) 120.03,36.76 U4.12 116.72,36.76 U4.PAD ; 120.41,21.26 120.16,21.01 U6.12 116.72,21.01 ; v1(115.95,35.79) 115.91,35.76 U4.7 112.81,35.76 v1(112.79,35.74) ; 116.47,20.01 U6.7
  TOP w0.279: 116.72,21.01 U6.PAD
  TOP w0.3: U1.15 81.42,59.11 81.42,57.45 81.17,57.2 v1(81.17,57.07) ; 85.32,57.85 85.32,57.8 v1(84.99,57.46)
  TOP w0.305: C11.2 v1(89.55,68.36)
  TOP w0.351: U1.18 83.37,57.83 v1(83.7,57.5) 84.02,57.83 U1.19 ; U1.21 85.32,57.85 84.99,57.52 v1(84.99,57.46) 84.67,57.78 U1.20
  TOP w0.5: v1(89.34,59.59) C14.1 ; U7.2 v1(105.01,18.51) ; C7.1 v1(78.08,18.01) ; U2.4 78.97,18.39 ; 115.26,16.17 115.26,16.18 ; v1(115.84,39.29) 116.09,39.29 116.47,38.91 116.47,38.31 v1(116.15,37.99) ; C34.2 v1(124.22,36.88)
  TOP w0.508: C52.2 131.73,16.99 ; C52.2 128.96,16.99 ; C52.2 130.35,15.81 ; C52.2 130.35,18.17 ; DS4.C 115.22,86.6 ; DS4.C 116.04,85.83 ; DS4.C 115.22,85.05 ; P8.1 149.66,28.1 ; P8.1 147.95,29.81 ; P8.1 146.24,28.1 ; P8.1 147.95,26.39 ; C12.1 79.22,55.79 ; C12.1 v1(77.14,55.79) ; C12.1 78.37,55.76 v1(79.47,55.76) ; P5.5 79.47,96.86 ; P5.5 79.47,94.45 ; P5.5 78.27,95.66 ; P5.5 80.68,95.66 ; 87.09,86.41 R61.2 ; R61.2 87.97,87.18 ; R61.2 87.09,87.96 ; 123.49,20.38 C32.2 122.64,21.25 ; C5.1 85.23,55.67 ; C5.1 84.38,56.55 ; C5.1 84.38,54.8 ; 109.57,59.35 R16.2 ; R16.2 108.69,60.12 ; R16.2 110.44,60.12 ; R16.2 109.57,60.9 ; 88.42,87.28 C17.2 89.29,86.44 ; 146.23,51.74 P4.1 ; P4.1 147.94,50.03 ; P4.1 149.66,51.74 ; P4.1 147.94,53.45 ; 101.49,47.61 R68.2 ; R68.2 101.49,49.36 ; R68.2 100.71,48.49 ; v1(109.57,20.44) 109.62,20.39 C39.2 ; 101.61,34.54 TP_GND2.1 ; TP_GND2.1 103.07,33.08 ; TP_GND2.1 104.53,34.54 ; TP_GND2.1 103.07,36 ; R33.2 115.6,48.49 ; R33.2 114.83,47.61 ; R33.2 114.05,48.49 ; R33.2 114.83,49.36 ; 122.79,17.73 R34.2 ; R34.2 121.89,18.81 ; R34.2 123.69,18.81 ; 122.17,38.32 R52.2 ; R52.2 123.25,39.22 ; R52.2 124.32,38.32 ; J1.3 66,44.83 ; J1.3 64.6,43.44 ; J1.3 67.39,43.44 ; J1.3 66,42.04 ; C38.2 116.19,32.99 ; C38.2 115.35,32.11 ; C38.2 115.35,33.86 ; 59.06,50.15 U3.12 61.24,50.15 ; 117.2,75.13 A1.10 ; A1.10 116.41,75.7 ; A1.10 117.98,75.7 ; A1.10 117.2,76.27 ; R64.2 83.28,87.96 ; R64.2 83.28,86.41 ; R64.2 84.16,87.18 ; 122.45,35.06 R73.2 ; R73.2 123.35,33.98 ; R73.2 124.25,35.06 ; R23.2 157.99,79.76 ; R23.2 155.48,79.76 ; R23.2 156.74,80.66 ; R23.2 156.74,78.86 ; 66,36.94 J1.4 ; J1.4 64.6,38.34 ; J1.4 66,39.73 ; J1.4 67.39,38.34 ; TP_GND3.1 129.81,69.96 ; TP_GND3.1 128.35,68.5 ; TP_GND3.1 129.81,67.04 ; TP_GND3.1 131.26,68.5 ; P2.2 98.66,6.05 ; P2.2 97.46,7.25 ; P2.2 97.46,4.85 ; P2.2 96.25,6.05 ; 85.48,86.44 C6.2 84.61,87.28 ; 90.9,86.41 R63.2 ; R63.2 91.78,87.18 ; R63.2 90.9,87.96 ; 111.66,7.1 111.66,9.15 ; 154.18,71.44 R24.2 ; R24.2 155.43,72.34 ; R24.2 152.92,72.34 ; R24.2 154.18,73.24 ; 112.85,75.3 R19.2 ; R19.2 115.01,75.3 ; R19.2 113.93,76.2 ; J1.5 62.29,38.34 ; J1.5 60.9,36.94 ; J1.5 60.9,39.73 ; J1.5 59.5,38.34 ; 89.56,37.17 C30.1 ; C30.1 91.31,37.17 ; C30.1 90.44,38.02 ; 155.46,72.34 C25.2 ; C25.2 158.02,72.34 ; C25.2 156.74,73.29 ; C25.2 156.74,71.39 ; 119.04,15.52 R51.2 ; R9.2 91.49,78.66 ; R9.2 90.8,77.91 ; R9.2 90.8,79.41 ; DS3.C 84.14,27.2 ; DS3.C 84.96,26.43 ; DS3.C 84.14,25.66 ; R71.2 119.06,30.4 ; R71.2 117.31,30.4 ; R71.2 118.19,31.17 ; R71.2 118.19,29.62 ; 154.18,78.81 C24.2 ; C24.2 154.18,80.71 ; C24.2 155.46,79.76 ; C24.2 152.9,79.76 ; 77.21,19.24 C7.1 ; 112.99,17.19 C37.2 112.15,16.31 ; v1(63.22,59.17) 62.99,58.94 C31.2 61.9,59.04 U3.19 ; 94.32,76.37 TP_GND1.1 ; TP_GND1.1 94.32,79.29 ; TP_GND1.1 95.78,77.83 ; TP_GND1.1 92.86,77.83 ; 93.11,86.44 C4.2 92.23,87.28 ; R60.2 95.59,87.18 ; R60.2 94.71,86.41 ; R60.2 94.71,87.96 ; 59.06,48.88 U3.11 ; U3.11 60.15,48.22 ; U3.11 61.24,48.88 ; U3.11 60.13,48.91 R6.2 56.43,48.91 ; 80.37,17.7 U2.4 81.84,18.39 ; 116.51,14.74 R70.2 ; R70.2 117.39,13.97 ; R70.2 117.39,15.52 ; R70.2 118.26,14.74 ; 87.11,17.97 C9.1 ; R32.2 103.54,78.42 ; R32.2 104.41,77.65 ; R32.2 103.54,76.88 ; R32.2 102.66,77.65 ; 80.46,4.85 P1.2 80.46,7.25 ; 59.5,43.44 J1.2 ; J1.2 60.9,42.04 ; J1.2 62.29,43.44 ; J1.2 60.9,44.83 ; 81.67,86.44 C18.2 80.79,87.28 ; P4.2 163.94,53.45 ; P4.2 165.66,51.74 ; P4.2 163.94,50.03 ; P4.2 162.23,51.74 ; 111.66,9.6 S1.5 111.66,11.65 ; P8.2 163.95,29.81 ; P8.2 165.66,28.1 ; P8.2 162.23,28.1 ; P8.2 163.95,26.39 ; 68.66,18.35 DS2.C ; DS2.C 70.21,18.35 ; DS2.C 69.44,17.53 ; U6.PAD 116.47,20.01 ; U7.2 105.01,20.9
  TOP w0.599: R9.2 90.81,78.67 v1(91.69,78.67)
  TOP w0.749: C9.1 89.22,17.97 v1(89.26,18.01)
  TOP w1.001: v1(115.4,75.3) 113.93,75.3 R19.2 ; C28.N 82.09,41.04 v1(82.05,41.07)
  L2_GND w0.508: 60.9,42.04 J1.2 ; J1.2 59.5,43.44 ; J1.2 62.29,43.44 ; J1.2 60.9,44.83 ; 64.6,43.44 J1.3 ; J1.3 66,44.83 ; J1.3 66,42.04 ; J1.3 67.39,43.44 ; P4.1 149.66,51.74 ; P4.1 147.94,53.45 ; P4.1 147.94,50.03 ; P4.1 146.23,51.74 ; P8.2 165.66,28.1 ; P8.2 162.23,28.1 ; P8.2 163.95,29.81 ; P8.2 163.95,26.39 ; P2.2 98.66,6.05 ; P2.2 97.46,4.85 ; P2.2 97.46,7.25 ; P2.2 96.25,6.05 ; 78.27,95.66 P5.5 ; P5.5 80.68,95.66 ; P5.5 79.47,94.45 ; P5.5 79.47,96.86 ; 66,36.94 J1.4 ; J1.4 64.6,38.34 ; J1.4 66,39.73 ; J1.4 67.39,38.34 ; 129.81,67.04 TP_GND3.1 ; TP_GND3.1 131.26,68.5 ; TP_GND3.1 129.81,69.96 ; TP_GND3.1 128.35,68.5 ; 147.95,26.39 P8.1 ; P8.1 149.66,28.1 ; P8.1 146.24,28.1 ; P8.1 147.95,29.81 ; 59.5,38.34 J1.5 ; J1.5 62.29,38.34 ; J1.5 60.9,39.73 ; J1.5 60.9,36.94 ; 79.25,6.05 P1.2 ; P1.2 80.46,7.25 ; P1.2 81.66,6.05 ; P1.2 80.46,4.85 ; TP_GND1.1 94.32,79.29 ; TP_GND1.1 94.32,76.37 ; TP_GND1.1 95.78,77.83 ; TP_GND1.1 92.86,77.83 ; TP_GND2.1 103.07,36 ; TP_GND2.1 104.53,34.54 ; TP_GND2.1 103.07,33.08 ; TP_GND2.1 101.61,34.54 ; 111.66,7.1 111.66,9.15 ; 111.66,9.6 S1.5 111.66,11.65 ; P4.2 165.66,51.74 ; P4.2 163.94,50.03 ; P4.2 163.94,53.45 ; P4.2 162.23,51.74
  L3_PWR w0.508: 97.46,4.85 P2.2 ; P2.2 96.25,6.05 ; P2.2 98.66,6.05 ; 59.5,38.34 J1.5 ; J1.5 60.9,36.94 ; J1.5 62.29,38.34 ; J1.5 60.9,39.73 ; P4.1 149.66,51.74 ; P4.1 147.94,53.45 ; P4.1 146.23,51.74 ; P4.1 147.94,50.03 ; P8.1 147.95,29.81 ; P8.1 146.24,28.1 ; P8.1 149.66,28.1 ; P8.1 147.95,26.39 ; P5.5 80.68,95.66 ; P5.5 79.47,94.45 ; P5.5 78.27,95.66 ; P5.5 79.47,96.86 ; 162.23,51.74 P4.2 ; P4.2 163.94,50.03 ; P4.2 165.66,51.74 ; P4.2 163.94,53.45 ; TP_GND3.1 129.81,69.96 ; TP_GND3.1 129.81,67.04 ; TP_GND3.1 128.35,68.5 ; TP_GND3.1 131.26,68.5 ; J1.3 66,44.83 ; J1.3 64.6,43.44 ; J1.3 66,42.04 ; J1.3 67.39,43.44 ; 59.5,43.44 J1.2 ; J1.2 60.9,42.04 ; J1.2 60.9,44.83 ; J1.2 62.29,43.44 ; 162.23,28.1 P8.2 ; P8.2 165.66,28.1 ; P8.2 163.95,29.81 ; P8.2 163.95,26.39 ; 80.46,4.85 P1.2 ; P1.2 81.66,6.05 ; P1.2 79.25,6.05 ; 66,36.94 J1.4 ; J1.4 66,39.73 ; J1.4 67.39,38.34 ; J1.4 64.6,38.34
  BOTTOM w0.508: 78.27,95.66 P5.5 ; P5.5 80.68,95.66 ; P5.5 79.47,96.86 ; P5.5 79.47,94.45 ; 94.32,76.37 TP_GND1.1 ; TP_GND1.1 94.32,79.29 ; TP_GND1.1 92.86,77.83 ; TP_GND1.1 95.78,77.83 ; J1.2 60.9,44.83 ; J1.2 62.29,43.44 ; J1.2 60.9,42.04 ; J1.2 59.5,43.44 ; J1.4 66,39.73 ; J1.4 66,36.94 ; J1.4 67.39,38.34 ; J1.4 64.6,38.34 ; 101.61,34.54 TP_GND2.1 ; TP_GND2.1 103.07,33.08 ; TP_GND2.1 103.07,36 ; TP_GND2.1 104.53,34.54 ; P8.1 149.66,28.1 ; P8.1 147.95,29.81 ; P8.1 147.95,26.39 ; P4.2 165.66,51.74 ; P4.2 163.94,50.03 ; P4.2 162.23,51.74 ; P4.2 163.94,53.45 ; 64.6,43.44 J1.3 ; J1.3 66,44.83 ; J1.3 66,42.04 ; J1.3 67.39,43.44 ; 96.25,6.05 P2.2 ; P2.2 97.46,7.25 ; P2.2 97.46,4.85 ; P2.2 98.66,6.05 ; J2.4 166.35,74.23 ; 111.66,11.65 S1.5 111.66,9.6 ; 79.25,6.05 P1.2 ; P1.2 81.66,6.05 ; P1.2 80.46,4.85 ; P1.2 80.46,7.25 ; P4.1 147.94,53.45 ; P4.1 147.94,50.03 ; P4.1 149.66,51.74 ; TP_GND3.1 131.26,68.5 ; TP_GND3.1 128.35,68.5 ; TP_GND3.1 129.81,67.04 ; TP_GND3.1 129.81,69.96 ; 162.23,28.1 P8.2 ; P8.2 165.66,28.1 ; P8.2 163.95,26.39 ; P8.2 163.95,29.81 ; J1.5 60.9,39.73 ; J1.5 60.9,36.94 ; J1.5 62.29,38.34 ; J1.5 59.5,38.34 ; R45.2 117.2,23.62 ; R45.2 116.43,22.75 ; R45.2 115.66,23.62 ; R45.2 116.43,24.5 ; 111.66,9.15 111.66,7.1 ; 114.83,38.4 R49.2 ; R49.2 114.83,40.15 ; R49.2 114.05,39.27 ; R49.2 115.6,39.27 ; 166.35,77.76 J2.2
  BOTTOM w1.001: v1(163.33,73.2) 163.37,73.16 J2.4 166.35,71.58 v1(166.38,71.55) ; v1(166.38,80.44) 166.35,80.41 J2.2 163.37,78.83 v1(163.33,78.79)
  vias: v1(58.95,21.54) v1(60,47.73) v1(61.81,49.34) v1(62.77,16.18) v1(63.1,2.64) v1(67.62,64.36) v1(67.82,62.75) v1(69.03,65.16) v1(69.55,43.79) v1(69.64,17.63) v1(70.5,97.46) v1(70.75,48.19) v1(71.24,33.08) v1(71.39,86.28) v1(71.35,68.24) v1(71.45,78.94) v1(71.4,72.19) v1(72.75,9.29) v1(73.16,35.23) v1(73.2,18.94) v1(73.45,98.5) v1(73.6,3.59) v1(74.45,33.28) v1(74.56,35.23) v1(75.86,74.02) v1(75.96,35.23) v1(76.34,48.99) v1(76.47,81.2) v1(77.36,35.23) v1(77.86,33.28) v1(78.05,50.19) v1(78.34,22.83) v1(78.45,98.5) v1(78.5,91.99) v1(78.65,1.55) v1(78.84,15.85) v1(80.37,14.2) v1(80.37,13.18) v1(80.37,12.16) v1(81.42,97.2) v1(81.48,85.86) v1(81.55,76.12) v1(81.89,15.85) v1(82.05,42.47) v1(82.05,39.67) v1(82.82,71.04) v1(82.9,1.55) v1(83.35,48.19) v1(83.45,98.5) v1(83.48,85.86) v1(83.42,22.83) v1(84.28,56.76) v1(84.28,54.55) v1(85.29,72.41) v1(85.49,85.86) v1(85.89,40.91) v1(86.29,69.2) v1(86.89,17.63) v1(87.01,42.59) v1(87.14,53.59) v1(87.29,85.86) v1(88.1,50.14) v1(88.45,98.5) v1(89.3,85.86) v1(90.02,23.09) v1(90.44,39.55) v1(90.4,1.55) v1(90.51,38.3) v1(91,85.98) v1(91.96,97.58) v1(92.72,37.89) v1(93.45,98.5) v1(93.45,80) v1(94.18,86.1) v1(94.5,60.88) v1(94.5,59.48) v1(95.19,86.1) v1(95.4,1.55) v1(95.92,67.4) v1(95.92,63.18) v1(96.79,40.56) v1(96.97,15.98) v1(97.35,87.75) v1(98.24,90.42) v1(98.45,98.5) v1(98.53,9.37) v1(98.66,15.21) v1(98.93,64.19) v1(98.93,13.22) v1(99.42,18.13) v1(100.08,11.5) v1(100.14,48.53) v1(100.4,1.55) v1(100.72,65.96) v1(101.34,17.43) v1(101.87,96.44) v1(101.94,20.64) v1(103.45,98.5) v1(103.45,1.5) v1(103.55,79.03) v1(103.74,10.13) v1(104.75,62.98) v1(104.91,35.61) v1(105.26,7.33) v1(105.35,38.89) v1(105.4,1.55) v1(106.26,12.52) v1(106.44,32.81) v1(106.95,76.12) v1(106.95,55.8) v1(108.45,98.5) v1(108.45,1.5) v1(108.56,36.49) v1(108.82,15.21) v1(108.82,5.05) v1(109.49,91.36) v1(109.57,58.77) v1(109.99,55.29) v1(109.97,35.29) v1(110.9,40.69) v1(111.17,73.79) v1(112.03,86.28) v1(112.03,5) v1(112.58,75.42) v1(112.95,73.13) v1(113.45,98.5) v1(113.45,81) v1(113.45,80.25) v1(113.45,71.5) v1(113.45,70.75) v1(113.45,70) v1(113.45,69.25) v1(113.45,1.5) v1(113.68,51.99) v1(113.7,73.19) v1(113.78,16.63) v1(114.08,17.89) v1(114.2,81) v1(114.2,80.25) v1(114.2,71.5) v1(114.2,70.75) v1(114.2,70) v1(114.2,69.25) v1(114.2,68.5) v1(114.45,73.19) v1(114.95,89.59) v1(114.95,81) v1(114.95,80.25) v1(114.95,71.5) v1(114.95,70.75) v1(114.95,70) v1(114.95,69.25) v1(114.95,68.5) v1(114.95,67.75) v1(115.19,87.06) v1(115.19,84.65) v1(115.15,34.39) v1(115.2,73.19) v1(115.39,31.48) v1(115.48,17.89) v1(115.7,81) v1(115.7,80.25) v1(115.7,78.13) v1(115.76,76.44) v1(115.7,71.5) v1(115.7,70.75) v1(115.7,70) v1(115.7,69.25) v1(115.7,68.5) v1(115.7,67.75) v1(115.9,22.35) v1(115.9,21.21) v1(115.9,20.19) v1(115.95,73.19) v1(115.95,53.99) v1(115.95,34.79) v1(116.13,74.81) v1(116.15,40.39) v1(116.15,36.99) v1(116.2,75.7) v1(116.39,32.88) v1(116.45,81) v1(116.45,80.25) v1(116.45,78.13) v1(116.45,71.5) v1(116.45,70.75) v1(116.45,70) v1(116.45,69.25) v1(116.45,68.5) v1(116.51,76.44) v1(116.55,33.79) v1(116.53,21.84) v1(116.53,20.7) v1(116.76,73.19) v1(116.85,89.29) v1(116.85,88.53) v1(116.85,87.77) v1(116.85,87.01) v1(116.85,86.24) v1(116.85,85.48) v1(116.85,84.72) v1(116.82,74.88) v1(116.98,37.99) v1(116.95,36.99) v1(116.95,35.79) v1(116.95,34.79) v1(117.04,22.35) v1(117.04,21.21) v1(117.04,20.19) v1(117.19,62.18) v1(117.19,60.98) v1(117.14,40.39) v1(117.14,39.39) v1(117.11,30.4) v1(117.2,81) v1(117.2,80.25) v1(117.2,78.13) v1(117.23,76.44) v1(117.2,71.5) v1(117.2,70.75) v1(117.2,70) v1(117.2,69.25) v1(117.39,13.42) v1(117.64,74.88) v1(117.64,73.19) v1(117.95,81) v1(117.95,80.25) v1(117.95,78.13) v1(117.95,71.25) v1(117.95,70) v1(118.05,83.43) v1(118.05,82.67) v1(118.05,81.91) v1(118.07,76.38) v1(118.2,72) v1(118.45,98.5) v1(118.45,75.7) v1(118.45,75) v1(118.45,74.25) v1(118.45,73.5) v1(118.45,72.75) v1(118.45,69.56) v1(118.45,1.5) v1(118.7,80.63) v1(118.75,56.59) v1(118.8,50.54) v1(118.95,78.25) v1(118.95,76) v1(118.95,72) v1(119.07,79.94) v1(119.01,67.87) v1(119.2,69.56) v1(119.2,15.02) v1(119.39,75) v1(119.39,74.31) v1(119.39,73.63) v1(119.39,72.94) v1(119.57,77.69) v1(119.57,76.75) v1(119.57,70.31) v1(119.52,66.85) v1(119.52,65.58) v1(119.63,71.13) v1(119.65,45.64) v1(119.7,76) v1(119.7,72) v1(119.82,79.94) v1(119.92,62.14) v1(119.92,60.87) v1(120.07,75) v1(120.07,74.31) v1(120.07,73.63) v1(120.07,72.94) v1(120.45,76) v1(120.45,72) v1(120.45,68.25) v1(120.6,82.25) v1(120.63,79.75) v1(120.82,75) v1(120.82,74.31) v1(120.82,73.63) v1(120.82,72.94) v1(120.8,11.58) v1(121.2,76) v1(121.26,69.56) v1(121.2,68.75) v1(121.3,80.95) v1(121.3,80.19) v1(121.32,79.31) v1(121.32,78.5) v1(121.32,77.69) v1(121.32,76.81) v1(121.32,71.25) v1(121.32,70.31) v1(121.45,72) v1(121.51,75) v1(121.51,74.31) v1(121.51,73.63) v1(121.51,72.94) v1(121.61,38.5) v1(121.95,76) v1(121.95,69.63) v1(121.95,68.75) v1(121.95,68) v1(122.01,66.79) v1(122.01,65.59) v1(122.19,96.44) v1(122.19,5) v1(122.45,75.25) v1(122.45,74.5) v1(122.45,73.75) v1(122.45,73) v1(122.45,72.25) v1(122.41,48.53) v1(122.7,76) v1(122.82,71.5) v1(122.82,69.94) v1(123.06,22.73) v1(123.2,74.88) v1(123.26,73.13) v1(123.21,33.48) v1(123.45,98.5) v1(123.45,1.5) v1(123.7,76.75) v1(124.02,18.84) v1(124.15,51.59) v1(124.26,80.69) v1(124.26,79.94) v1(124.22,20.44) v1(124.32,81.44) v1(124.32,79.13) v1(124.32,78.31) v1(124.38,77.31) v1(124.32,73.19) v1(124.42,38.3) v1(124.6,35.1) v1(124.95,81.44) v1(124.95,80.69) v1(124.95,79.88) v1(125.13,79.13) v1(125.13,78.31) v1(125.13,77.5) v1(125.13,73) v1(125.11,18.21) v1(125.65,90.39) v1(125.62,66.22) v1(125.62,65.45) v1(125.7,72.38) v1(125.7,71.63) v1(125.7,70.88) v1(125.7,70.13) v1(125.7,69.38) v1(125.7,68.5) v1(125.7,67.75) v1(125.7,67) v1(126.15,34.59) v1(126.38,74.22) v1(126.89,74.6) v1(126.95,73.75) v1(127.39,74.22) v1(127.39,73.2) v1(127.39,72.44) v1(127.39,71.68) v1(127.39,70.91) v1(127.39,70.15) v1(127.39,69.39) v1(127.39,68.63) v1(127.39,67.87) v1(127.39,67.1) v1(127.39,66.34) v1(127.39,65.58) v1(127.55,34.39) v1(128.45,98.5) v1(128.45,1.5) v1(128.63,17.03) v1(129.63,63.18) v1(129.63,35.49) v1(129.81,70.41) v1(129.81,66.6) v1(129.99,90.44) v1(130.24,15.22) v1(130.31,81.71) v1(130.31,80.44) v1(130.31,79.17) v1(130.44,48.13) v1(130.63,55.12) v1(130.64,33.89) v1(132.04,35.49) v1(132.04,16.83) v1(132.28,58.93) v1(132.35,96.44) v1(132.35,5) v1(133.45,98.5) v1(133.45,1.5) v1(133.68,48.49) v1(133.84,15.19) v1(136.46,90.07) v1(136.45,20.29) v1(136.79,72.95) v1(136.98,47.11) v1(137.05,11.78) v1(137.46,42.51) v1(137.65,95.46) v1(137.66,54.15) v1(137.66,20.04) v1(138.26,64.59) v1(138.45,98.5) v1(138.46,14.99) v1(138.45,1.5) v1(138.66,45.32) v1(139.47,18.44) v1(139.55,31.79) v1(140.47,42.92) v1(140.87,20.24) v1(142.21,28.79) v1(142.51,96.44) v1(142.51,65.96) v1(142.51,45.64) v1(142.51,5) v1(142.95,13.84) v1(143.45,98.5) v1(143.45,1.5) v1(147.59,91.36) v1(147.59,60.88) v1(147.59,10.08) v1(148.45,98.5) v1(148.45,1.5) v1(149.1,21.04) v1(150.75,54.19) v1(152.67,45.64) v1(152.67,35.48) v1(152.67,25.32) v1(152.75,19.19) v1(152.75,13.39) v1(153.45,98.5) v1(153.45,1.5) v1(154.11,81.04) v1(154.11,71.21) v1(155.21,86.28) v1(155.75,67.19) v1(156.72,81.04) v1(156.72,71.01) v1(157.75,71.04) v1(157.75,56.88) v1(157.75,46.72) v1(157.75,36.56) v1(157.75,10.08) v1(158.45,98.5) v1(159.15,1.19) v1(161.74,1.19) v1(162.75,98.6) v1(162.83,31.48) v1(162.83,21.32) v1(164.75,67.19) v1(166.75,6.19) v1(166.95,98.5) v1(166.95,90) v1(166.95,85) v1(166.95,70) v1(166.95,61) v1(166.95,56) v1(166.95,46) v1(166.95,36) v1(166.95,31) v1(166.95,26) v1(166.95,21) v1(166.95,16) v1(166.95,13.39) v1(166.95,10) v1(166.95,1.5) v1(167.35,94.39)
GND_ISO: length 88.2
  TOP w0.305: v1(51.94,59.04) U3.2 48.66,59.04 C10.2
  TOP w0.351: v1(16.86,65.9) U5.7
  TOP w0.381: U3.10 v1(51.94,48.88)
  TOP w0.5: U5.4 v1(25.37,68.44) ; C29.2 16.77,65.81 v1(16.86,65.9) ; U5.3 v1(25.37,67.17) ; U5.2 v1(25.37,65.9)
  TOP w0.508: 4.1,61.07 P11.5 6.5,61.07 ; P14.7 27.53,29.13 ; P14.7 27.53,26.72 ; P14.7 26.32,27.93 ; 21.99,68.44 U5.4 23.46,69.12 ; R41.1 25.55,63.47 ; R41.1 26.25,62.73 ; R41.1 25.55,61.98 ; U5.7 19.85,65.9 ; 10.76,74.98 P17.7 10.76,77.39 ; P14.6 24.99,29.13 ; P14.6 24.99,26.72 ; P14.6 26.19,27.93 ; v1(51.94,48.88) 51.96,48.91 R6.1 54.73,48.91 ; 50.53,48.22 U3.10 49.44,48.88 ; 5.16,30.65 DS1.C ; DS1.C 5.98,31.42 ; DS1.C 5.98,29.87 ; 21.99,67.17 U5.3 ; 47.69,58.94 C10.2 ; 1.56,61.07 P11.11 3.96,61.07 ; 15.1,65.81 C29.2 ; 21.99,65.9 U5.2
  L2_GND w0.508: 24.99,26.72 P14.6 ; P14.6 24.99,29.13 ; P14.6 26.19,27.93 ; 27.53,26.72 P14.7 ; P14.7 27.53,29.13 ; P14.7 26.32,27.93 ; 10.76,77.39 P17.7 10.76,74.98 ; 6.5,61.07 P11.5 4.1,61.07 ; 3.96,61.07 P11.11 1.56,61.07
  L3_PWR w0.508: 26.32,27.93 P14.7 ; P14.7 27.53,26.72 ; P14.7 27.53,29.13 ; 24.99,26.72 P14.6 ; P14.6 24.99,29.13 ; P14.6 26.19,27.93 ; 6.5,61.07 P11.5 4.1,61.07 ; 10.76,74.98 P17.7 10.76,77.39 ; 1.56,61.07 P11.11 3.96,61.07
  BOTTOM w0.508: P14.7 27.53,29.13 ; P14.7 26.32,27.93 ; P14.7 27.53,26.72 ; 10.76,77.39 P17.7 10.76,74.98 ; P14.6 26.19,27.93 ; P14.6 24.99,29.13 ; P14.6 24.99,26.72 ; 3.96,61.07 P11.11 1.56,61.07 ; 6.5,61.07 P11.5 4.1,61.07
  vias: v1(1.42,44.87) v1(1.42,39.87) v1(1.42,34.87) v1(1.42,29.88) v1(1.42,24.87) v1(4.34,23.59) v1(4.82,30.68) v1(8.94,32.63) v1(10.63,73.27) v1(11.37,50.16) v1(12.34,23.59) v1(14.66,65.99) v1(16.47,43.89) v1(18.89,34.74) v1(18.82,23.59) v1(19.54,62.79) v1(20.34,78.5) v1(22.55,50.16) v1(23.64,23.9) v1(25.11,40.88) v1(25.69,63.78) v1(26.38,71.36) v1(26.89,36.62) v1(27.65,48.5) v1(28.64,23.9) v1(28.84,78.5) v1(31.34,43.39) v1(31.46,77.58) v1(32.84,50.29) v1(33.49,36.24) v1(33.64,23.9) v1(33.84,78.5) v1(34.13,40.37) v1(35.91,41.32) v1(36.9,65.4) v1(37.01,46.13) v1(45.24,44.13) v1(45.45,78.5) v1(47.36,58.97) v1(47.46,45.77) v1(48.36,78.4) v1(48.49,68.03) v1(48.88,49.49) v1(48.82,24.13) v1(50.45,78.5) v1(50.57,47.93) v1(50.94,73.59) v1(51.4,62.15)
VCCHV_EXT: length 16
  TOP w2.499: P6.2 P6.1
VCCHV_LT8365: length 6.2
  TOP w1.001: v1(133.75,34.19) 133.75,35.79 ; 133.75,35.79 C45.1 ; 133.75,35.79 133.7,35.79 132.69,36.79 R42.2
  TOP w1.016: R46.1 v1(123.21,31.79) v1(124.22,31.79)
VCCISO_EXT: length 20.3
  TOP w0.5: R25.1 v1(21.81,62.73) ; C29.1 16.39,64.63 U5.8
  TOP w0.508: 54.73,60.31 R5.1 U3.1 48.79,60.31 C10.1 ; R10.1 v1(37.69,71.78) ; R26.2 12.9,30.74 v1(12.9,31.8) ; R7.1 v1(46.55,51.92) ; R8.1 v1(32.61,71.78) ; R59.1 v1(11.08,31.85)
  TOP w1.001: v1(11.27,63.61) R1.2 10.44,62.54 v1(10.51,62.47) ; v1(15.06,64.21) C29.1 ; 48.23,61.95 v1(48.23,62.6)
  TOP w1.016: C10.1 48.23,60.87 48.23,61.95
VSSHV_EXT: length 16
  TOP w2.499: P7.2 P7.1
VSSHV_LT8365: length 4.6
  TOP w0.381: v1(126.89,18.59) 127.02,18.46 R44.1
  TOP w0.762: v1(140.73,23.34) 139.65,23.34 C53.1 R69.2
3P3V_EXT: length 7.2
  TOP w0.508: 91.99,22.07 JP2.3 ; JP2.3 93.2,23.27 ; JP2.3 93.2,20.87 ; 93.65,4.85 P2.1 ; P2.1 93.65,7.25 ; P2.1 92.44,6.05
3P3V_LDO: length 10.3
  TOP w1.001: U7.4 105.96,22.9 105.64,23.21 103.99,23.21 ; 103.99,23.21 102.12,23.21 C47.1 99.46,23.25 JP2.1 ; 103.99,23.21 104.06,23.15 U7.5
A1_SHUTDOWN_N: length 46.1
  TOP w0.249: A1.8 120.45,78.5 119.91,79.04 v1(112.15,79.04)
  TOP w0.508: v1(112.15,79.04) 112.15,81.19 R66.1
  BOTTOM w0.254: v1(112.15,79.04) 108.22,75.11 JP4.2
BIN2SCOMP: length 14
  TOP w0.305: U1.5 84.67,67.17 84.09,67.76 JP3.2
CLR_N: length 91.8
  TOP w0.305: P16.5 R10.2 ; v1(37.41,50.13) 48.04,50.13 49.34,51.42 U3.8 R58.1 54.83,51.42
  BOTTOM w0.254: 1.98,52.19 7.69,52.19
  BOTTOM w0.305: P16.5 39.31,74.56 39.31,52.03 v1(37.41,50.13) 36.68,49.4 10.49,49.4 7.69,52.19 ; P11.10 1.47,57.24 1.47,52.7 1.98,52.19
CLR_N_DAC: length 46.9
  TOP w0.249: U1.11 80.77,64.9 80.77,65.94 80.32,66.39 R2.2
  TOP w0.305: 56.33,51.42 R58.2 U3.13 61.29,51.42 CLR_N.1 v1(74.65,46.9)
  TOP w0.5: v1(78.95,65.59) 78.95,66.29 R2.2
  BOTTOM w0.3: v1(78.95,65.59) 75.15,65.59 74.65,65.09 v1(74.65,46.9)
DACA: length 12.1
  TOP w0.305: R11.1 105.91,65.24 101.94,69.2 JP7.1
DACB: length 8.6
  TOP w0.305: JP8.1 96.6,72.33 R31.1
  TOP w0.381: R30.1 103.59,72.38 R31.1
DACC: length 14.4
  TOP w0.305: R13.1 105.91,59.32 99.94,53.35 JP9.1
DACD: length 10.7
  TOP w0.376: R68.1 103.19,47.17 102.75,46.73 JP10.1
  TOP w0.399: JP4.1 R68.1
HVOUT_SENSE: length 12.9
  TOP w0.762: R18.2 R67.2 ; R67.2 145.32,86.89 JP11.2 ; R67.2 145.58,87.23 C16.2 HVOUT_S.1
LDAC_N: length 83.8
  TOP w0.305: P16.7 R8.2 ; 54.83,52.69 R57.1 U3.7 49.08,52.69 47.44,51.05 v1(32.2,51.05)
  BOTTOM w0.254: 7.69,54.73 4.02,54.73
  BOTTOM w0.305: 4.02,54.73 P11.9 ; 7.69,54.73 11.37,51.05 v1(32.2,51.05) 34.23,53.08 34.23,74.56 P16.7
